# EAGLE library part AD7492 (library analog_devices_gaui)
Analog Devices AD7492 TSSOP-24 package By Gudjon I. Gudjonsson (gudjon@mc2.chalmers.se).
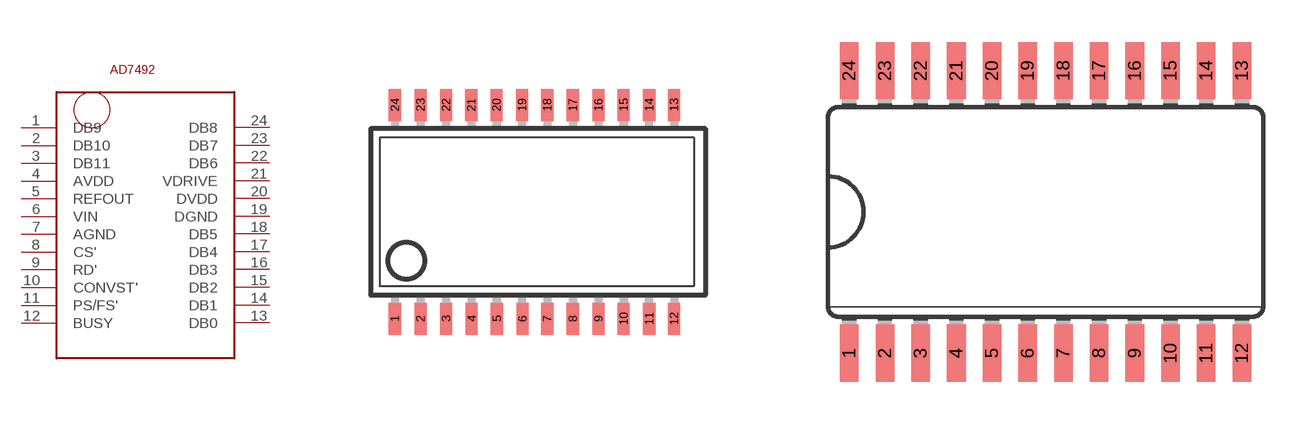
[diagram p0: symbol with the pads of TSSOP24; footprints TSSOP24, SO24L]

Designator prefix IC

## AD7492ARU  [TSSOP24]
1  DB9  out
2  DB10  out
3  DB11  out
4  AVDD  pwr
5  REFOUT  out
6  VIN  in
7  AGND  pwr
8  CS'  in
9  RD'  in
10  CONVST'  in
11  PS/FS'
12  BUSY
13  DB0  out
14  DB1  out
15  DB2  out
16  DB3  out
17  DB4  out
18  DB5  out
19  DGND  pwr
20  DVDD  pwr
21  VDRIVE
22  DB6  out
23  DB7  out
24  DB8  out

## AD7492AR  [SO24L]
Pads as for TSSOP24

## Footprint TSSOP24 (pad centres in mm)
smd 0.305 x 0.8: 1 1.74,0.8; 2 2.38,0.8; 3 3.02,0.8; 4 3.66,0.8; 5 4.29,0.8; 6 4.93,0.8; 7 5.55,0.8; 8 6.19,0.8; 9 6.83,0.8; 10 7.46,0.8; 11 8.1,0.8; 12 8.72,0.8; 13 8.72,6.15; 14 8.1,6.15; 15 7.46,6.15; 16 6.83,6.15; 17 6.19,6.15; 18 5.55,6.15; 19 4.92,6.15; 20 4.28,6.15; 21 3.65,6.15; 22 3.02,6.15; 23 2.38,6.15; 24 1.74,6.15

## Footprint SO24L (pad centres in mm)
Small Outline package large
smd 0.66 x 2.032: 1 -6.985,-5.029; 2 -5.715,-5.029; 3 -4.445,-5.029; 4 -3.175,-5.029; 5 -1.905,-5.029; 6 -0.635,-5.029; 7 0.635,-5.029; 8 1.905,-5.029; 9 3.175,-5.029; 10 4.445,-5.029; 11 5.715,-5.029; 12 6.985,-5.029; 13 6.985,5.029; 14 5.715,5.029; 15 4.445,5.029; 16 3.175,5.029; 17 1.905,5.029; 18 0.635,5.029; 19 -0.635,5.029; 20 -1.905,5.029; 21 -3.175,5.029; 22 -4.445,5.029; 23 -5.715,5.029; 24 -6.985,5.029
